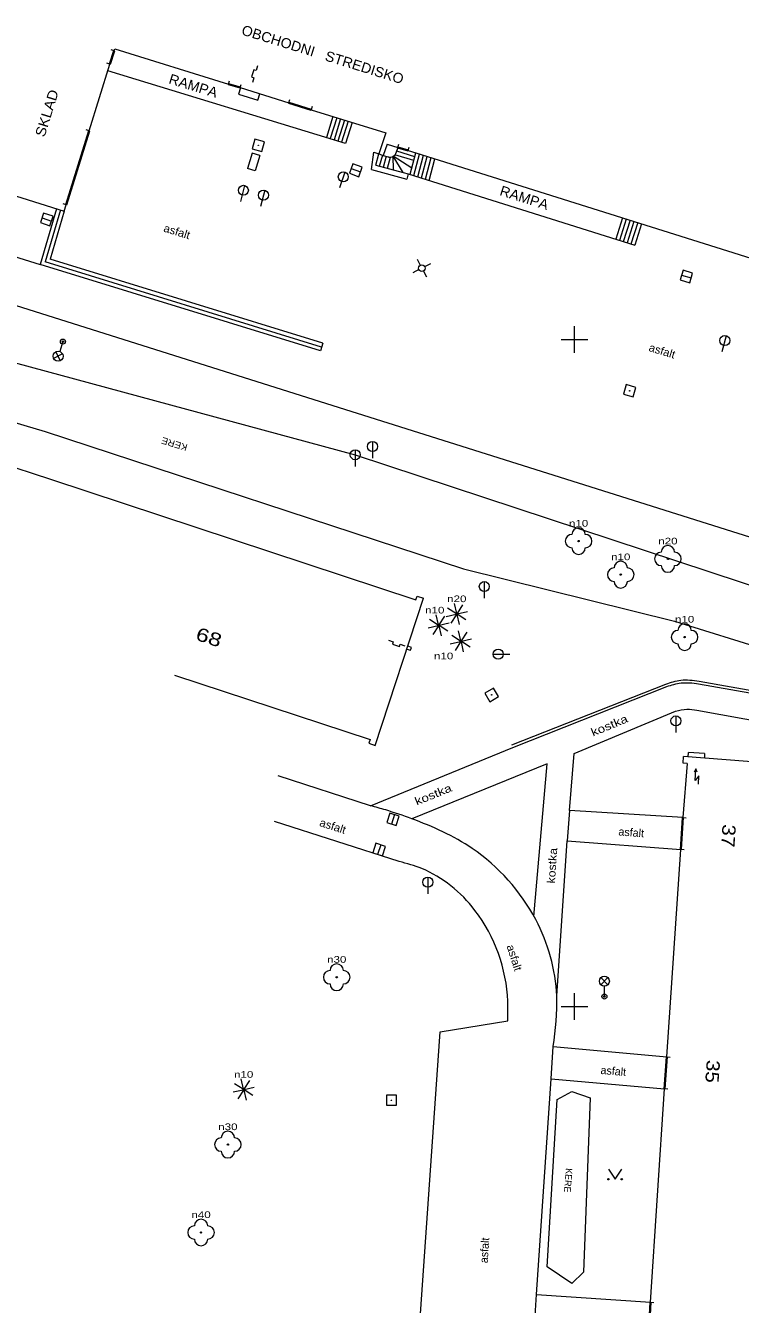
# Model space of a CAD drawing. Extents: x -670514 to -669423, y -1130798 to -1130123.
# Drawn here: x -670241.1 to -670187.6, y -1130272.3 to -1130176.5 of the extents above; entities that cross this region are included whole.
import ezdxf
from ezdxf.enums import TextEntityAlignment as Align

# ---------------------------------------------------------------- set-up
doc = ezdxf.new("R2010")
doc.units = 0
doc.header["$LTSCALE"] = 0.24
for name, color, linetype, lineweight in [('10', 7, 'Continuous', 13), ('11', 7, 'Continuous', 13), ('14', 7, 'Continuous', 13), ('21', 7, 'Continuous', 13), ('22', 7, 'Continuous', 13), ('24', 7, 'Continuous', 13), ('26', 7, 'Continuous', 13), ('27', 7, 'Continuous', 13), ('31', 7, 'Continuous', 13), ('33', 7, 'Continuous', 13), ('36', 7, 'Continuous', 13), ('5', 7, 'Continuous', 13), ('6', 7, 'Continuous', 13), ('61', 7, 'Continuous', 13), ('7', 7, 'Continuous', 13), ('9', 7, 'Continuous', 13)]:
    doc.layers.add(name, color=color, linetype=linetype, lineweight=lineweight)
for name, color, linetype in [('40', 7, 'Continuous'), ('41', 7, 'Continuous'), ('42', 7, 'Continuous'), ('44', 7, 'Continuous'), ('47', 7, 'Continuous')]:
    doc.layers.add(name, color=color, linetype=linetype)

msp = doc.modelspace()

# ---------------------------------------------------------------- linework, layer by layer
at = {"layer": '10'}
for p, q in [((-670217.167, -1130185.297), (-670234.972, -1130179.846)), ((-670218.107, -1130183.277), (-670218.598, -1130184.849)), ((-670217.821, -1130183.367), (-670218.312, -1130184.939)), ((-670217.535, -1130183.456), (-670218.026, -1130185.028)), ((-670217.248, -1130183.546), (-670217.739, -1130185.118)), ((-670216.962, -1130183.635), (-670217.453, -1130185.207)), ((-670216.676, -1130183.725), (-670217.167, -1130185.297)), ((-670271.263, -1130184.51), (-670240.044, -1130194.383)), ((-670215.221, -1130187.258), (-670215.048, -1130185.95)), ((-670215.048, -1130185.95), (-670214.669, -1130186.077)), ((-670214.896, -1130186.923), (-670214.669, -1130186.077)), ((-670214.606, -1130187), (-670214.379, -1130186.154)), ((-670214.342, -1130186.192), (-670213.96, -1130186.309)), ((-670214.316, -1130187.078), (-670214.089, -1130186.232)), ((-670213.566, -1130187.279), (-670213.595, -1130186.248)), ((-670212.837, -1130187.474), (-670213.595, -1130186.248)), ((-670212.203, -1130187.146), (-670213.595, -1130186.248)), ((-670212.053, -1130186.584), (-670213.458, -1130186.15)), ((-670213.235, -1130185.591), (-670213.391, -1130186.035)), ((-670211.975, -1130186.293), (-670213.323, -1130185.877)), ((-670212.327, -1130187.61), (-670211.898, -1130186.004)), ((-670212.042, -1130187.707), (-670211.612, -1130186.094)), ((-670211.756, -1130187.798), (-670211.325, -1130186.184)), ((-670211.469, -1130187.888), (-670211.038, -1130186.275)), ((-670214.896, -1130186.923), (-670212.837, -1130187.474)), ((-670214.026, -1130187.156), (-670213.803, -1130186.327)), ((-670211.183, -1130187.979), (-670210.752, -1130186.365)), ((-670210.896, -1130188.069), (-670210.465, -1130186.455)), ((-670215.221, -1130187.258), (-670212.579, -1130187.965)), ((-670212.837, -1130187.474), (-670212.474, -1130187.571)), ((-670212.474, -1130187.571), (-670212.579, -1130187.965)), ((-670212.474, -1130187.571), (-670195.49, -1130192.934)), ((-670196.414, -1130190.877), (-670196.92, -1130192.483)), ((-670196.128, -1130190.967), (-670196.634, -1130192.573)), ((-670195.842, -1130191.057), (-670196.348, -1130192.663)), ((-670195.556, -1130191.147), (-670196.062, -1130192.753)), ((-670195.27, -1130191.237), (-670195.776, -1130192.843)), ((-670194.984, -1130191.328), (-670195.49, -1130192.934)), ((-670216.254, -1130205.533), (-670257.775, -1130192.44)), ((-670164.577, -1130221.854), (-670216.254, -1130205.533)), ((-670190.705, -1130225.799), (-670161.27, -1130231.071)), ((-670190.834, -1130227.796), (-670161.644, -1130232.991)), ((-670215.282, -1130234.947), (-670222.22, -1130232.715)), ((-670213.137, -1130239.127), (-670222.492, -1130236.118)), ((-670191.884, -1130235.838), (-670200.384, -1130235.306)), ((-670210.077, -1130251.897), (-670205.001, -1130251.08)), ((-670212.326, -1130284.389), (-670210.077, -1130251.897)), ((-670201.594, -1130252.994), (-670193.086, -1130253.78)), ((-670201.752, -1130255.433), (-670193.25, -1130256.172)), ((-670203.011, -1130273.982), (-670202.849, -1130271.587)), ((-670202.849, -1130271.587), (-670194.302, -1130272.164))]:
    msp.add_line(p, q, dxfattribs=at)
for points in [[(-670215.282, -1130234.947), (-670204.632, -1130230.576), (-670193.082, -1130226.009)], [(-670200.384, -1130235.306), (-670200.036, -1130231.028), (-670192.434, -1130227.867)], [(-670203.041, -1130243.246), (-670202.049, -1130231.799), (-670212.195, -1130235.926)], [(-670201.332, -1130249.211), (-670200.558, -1130237.583), (-670192.04, -1130238.233)], [(-670202.849, -1130271.587), (-670201.752, -1130255.433), (-670201.594, -1130252.994)]]:
    msp.add_lwpolyline(points, dxfattribs=at)
for points in [[(-670213.96, -1130186.309), (-670213.924, -1130186.318), (-670213.455, -1130186.148), (-670213.419, -1130186.094), (-670213.391, -1130186.035)], [(-670193.082, -1130226.009), (-670192.021, -1130225.744), (-670190.705, -1130225.799)], [(-670192.434, -1130227.867), (-670191.576, -1130227.715), (-670190.834, -1130227.796)], [(-670201.594, -1130252.994), (-670201.332, -1130249.211), (-670202.91, -1130243.487), (-670207.671, -1130238.155), (-670212.195, -1130235.926), (-670214.153, -1130235.267), (-670215.282, -1130234.947)], [(-670205.001, -1130251.08), (-670205.001, -1130249.61), (-670207.465, -1130242.79), (-670211.445, -1130239.665), (-670213.137, -1130239.127)]]:
    msp.add_spline(points, degree=3, dxfattribs=at)
at = {"layer": '11'}
msp.add_line((-670200.384, -1130235.306), (-670200.558, -1130237.583), dxfattribs=at)
at = {"layer": '14'}
msp.add_line((-670192.5, -1130221.111), (-670161.234, -1130230.874), dxfattribs=at)
for points in [[(-670280.134, -1130185.532), (-670276.888, -1130192.263), (-670216.436, -1130208.635)], [(-670285.272, -1130193.354), (-670239.681, -1130206.896), (-670208.333, -1130217.194), (-670192.5, -1130221.111)], [(-670216.436, -1130208.635), (-670182.668, -1130219.789), (-670167.119, -1130226.229), (-670161.27, -1130231.071)]]:
    msp.add_lwpolyline(points, dxfattribs=at)
at = {"layer": '21'}
msp.add_lwpolyline([(-670201.31, -1130256.981), (-670200.193, -1130256.36), (-670198.826, -1130256.857), (-670199.323, -1130269.904), (-670200.193, -1130270.774), (-670202.057, -1130269.526)], close=True, dxfattribs=at)
at = {"layer": '22'}
for p, q in [((-670208.834, -1130220.532), (-670209.006, -1130219.778)), ((-670210.191, -1130221.382), (-670210.363, -1130220.628)), ((-670209.749, -1130220.732), (-670210.163, -1130221.388)), ((-670209.62, -1130220.752), (-670208.866, -1130220.58)), ((-670208.86, -1130220.552), (-670209.516, -1130220.138)), ((-670208.846, -1130220.606), (-670209.26, -1130221.262)), ((-670208.818, -1130220.612), (-670208.646, -1130221.366)), ((-670208.392, -1130219.882), (-670208.806, -1130220.538)), ((-670208.136, -1130221.006), (-670208.792, -1130220.592)), ((-670208.786, -1130220.564), (-670208.032, -1130220.392)), ((-670210.977, -1130221.602), (-670210.223, -1130221.43)), ((-670210.217, -1130221.402), (-670210.873, -1130220.988)), ((-670210.203, -1130221.456), (-670210.617, -1130222.112)), ((-670210.175, -1130221.462), (-670210.003, -1130222.216)), ((-670209.493, -1130221.856), (-670210.149, -1130221.442)), ((-670210.143, -1130221.414), (-670209.389, -1130221.242)), ((-670209.312, -1130222.801), (-670208.558, -1130222.629)), ((-670208.552, -1130222.601), (-670209.208, -1130222.187)), ((-670208.538, -1130222.655), (-670208.952, -1130223.311)), ((-670208.526, -1130222.581), (-670208.698, -1130221.827)), ((-670208.51, -1130222.661), (-670208.338, -1130223.415)), ((-670208.084, -1130221.931), (-670208.498, -1130222.587)), ((-670207.828, -1130223.055), (-670208.484, -1130222.641)), ((-670208.478, -1130222.613), (-670207.724, -1130222.441)), ((-670225.588, -1130256.407), (-670224.834, -1130256.235)), ((-670224.828, -1130256.207), (-670225.484, -1130255.793)), ((-670224.814, -1130256.261), (-670225.228, -1130256.917)), ((-670224.802, -1130256.187), (-670224.974, -1130255.433)), ((-670224.786, -1130256.267), (-670224.614, -1130257.021)), ((-670224.36, -1130255.537), (-670224.774, -1130256.193)), ((-670224.104, -1130256.661), (-670224.76, -1130256.247)), ((-670224.754, -1130256.219), (-670224, -1130256.047))]:
    msp.add_line(p, q, dxfattribs=at)
for centre, radius in [((-670199.697, -1130215.112), 0.05), ((-670193.005, -1130216.446), 0.05), ((-670196.541, -1130217.626), 0.05), ((-670208.826, -1130220.572), 0.04), ((-670210.183, -1130221.422), 0.04), ((-670208.518, -1130222.621), 0.04), ((-670191.753, -1130222.304), 0.05), ((-670217.824, -1130247.806), 0.05), ((-670224.794, -1130256.227), 0.04), ((-670225.98, -1130260.353), 0.05), ((-670227.99, -1130266.942), 0.05)]:
    msp.add_circle(centre, radius, dxfattribs=at)
for centre, start, end in [((-670200.197, -1130215.112), 90, 270), ((-670199.697, -1130214.612), 0, 180), ((-670199.197, -1130215.112), 270, 90), ((-670199.697, -1130215.612), 180, 0), ((-670193.505, -1130216.446), 90, 270), ((-670193.005, -1130215.946), 0, 180), ((-670192.505, -1130216.446), 270, 90), ((-670196.541, -1130217.126), 0, 180), ((-670193.005, -1130216.946), 180, 0), ((-670197.041, -1130217.626), 90, 270), ((-670196.041, -1130217.626), 270, 90), ((-670196.541, -1130218.126), 180, 0), ((-670191.753, -1130221.804), 0, 180), ((-670192.253, -1130222.304), 90, 270), ((-670191.253, -1130222.304), 270, 90), ((-670191.753, -1130222.804), 180, 0), ((-670218.324, -1130247.806), 90, 270), ((-670217.824, -1130247.306), 0, 180), ((-670217.324, -1130247.806), 270, 90), ((-670217.824, -1130248.306), 180, 0), ((-670226.48, -1130260.353), 90, 270), ((-670225.98, -1130259.853), 0, 180), ((-670225.48, -1130260.353), 270, 90), ((-670225.98, -1130260.853), 180, 0), ((-670228.49, -1130266.942), 90, 270), ((-670227.99, -1130266.442), 0, 180), ((-670227.49, -1130266.942), 270, 90), ((-670227.99, -1130267.442), 180, 0)]:
    msp.add_arc(centre, 0.5, start, end, dxfattribs=at)
at = {"layer": '24'}
for p, q in [((-670191.477, -1130231.281), (-670191.461, -1130230.961)), ((-670190.255, -1130231.022), (-670191.461, -1130230.961)), ((-670190.255, -1130231.022), (-670190.273, -1130231.378))]:
    msp.add_line(p, q, dxfattribs=at)
for points in [[(-670223.761, -1130179.491), (-670223.872, -1130179.842), (-670224.046, -1130179.787), (-670224.211, -1130180.314), (-670224.037, -1130180.37), (-670224.146, -1130180.721)], [(-670225.035, -1130181.121), (-670225.191, -1130181.617), (-670223.723, -1130182.055), (-670223.574, -1130181.577)], [(-670213.945, -1130222.548), (-670213.596, -1130222.664), (-670213.653, -1130222.838), (-670213.128, -1130223.01), (-670213.07, -1130222.836), (-670212.72, -1130222.95)], [(-670212.569, -1130223.203), (-670212.291, -1130223.293), (-670212.223, -1130223.084), (-670212.5, -1130222.993)], [(-670190.821, -1130232.439), (-670190.918, -1130232.189), (-670191.04, -1130232.428)], [(-670190.725, -1130233.326), (-670190.694, -1130232.701), (-670190.962, -1130233.063), (-670190.918, -1130232.189)]]:
    msp.add_lwpolyline(points, dxfattribs=at)
at = {"layer": '26'}
for points in [[(-670224.165, -1130185.695), (-670223.444, -1130185.9), (-670223.239, -1130185.179), (-670223.96, -1130184.974)], [(-670196.339, -1130204.103), (-670195.617, -1130204.307), (-670195.413, -1130203.585), (-670196.135, -1130203.381)], [(-670206.352, -1130227.149), (-670205.703, -1130226.772), (-670206.08, -1130226.123), (-670206.729, -1130226.5)], [(-670214.097, -1130257.404), (-670213.347, -1130257.404), (-670213.347, -1130256.654), (-670214.097, -1130256.654)]]:
    msp.add_lwpolyline(points, close=True, dxfattribs=at)
for centre in [(-670223.7019, -1130185.437), (-670195.8759, -1130203.844), (-670206.216, -1130226.636), (-670213.7219, -1130257.029)]:
    msp.add_circle(centre, 0.02, dxfattribs=at)
at = {"layer": '27'}
for p, q in [((-670216.75, -1130187.182), (-670216.046, -1130187.438)), ((-670217.208, -1130187.45), (-670217.621, -1130188.63)), ((-670224.723, -1130188.45), (-670225.041, -1130189.66)), ((-670223.218, -1130188.812), (-670223.541, -1130190.021)), ((-670239.908, -1130190.873), (-670239.198, -1130191.115)), ((-670191.975, -1130195.172), (-670191.255, -1130195.378)), ((-670188.64, -1130199.714), (-670188.976, -1130200.918)), ((-670216.436, -1130208.26), (-670216.436, -1130209.51)), ((-670215.145, -1130207.641), (-670215.145, -1130208.891)), ((-670206.763, -1130218.143), (-670206.763, -1130219.393)), ((-670206.097, -1130223.589), (-670204.847, -1130223.589)), ((-670192.408, -1130228.216), (-670192.408, -1130229.466)), ((-670213.492, -1130235.611), (-670213.722, -1130236.325)), ((-670214.526, -1130237.881), (-670214.756, -1130238.595)), ((-670210.996, -1130240.302), (-670210.996, -1130241.552))]:
    msp.add_line(p, q, dxfattribs=at)
for points in [[(-670216.878, -1130187.533), (-670216.174, -1130187.79), (-670215.917, -1130187.085), (-670216.622, -1130186.828)], [(-670240.029, -1130191.227), (-670239.319, -1130191.469), (-670239.077, -1130190.759), (-670239.787, -1130190.517)], [(-670192.079, -1130195.531), (-670191.358, -1130195.738), (-670191.151, -1130195.017), (-670191.872, -1130194.81)], [(-670213.848, -1130235.496), (-670214.078, -1130236.21), (-670213.364, -1130236.44), (-670213.134, -1130235.726)], [(-670214.882, -1130237.766), (-670215.112, -1130238.48), (-670214.398, -1130238.71), (-670214.168, -1130237.996)]]:
    msp.add_lwpolyline(points, close=True, dxfattribs=at)
for centre in [(-670217.3317, -1130187.8042), (-670224.8177, -1130188.8132), (-670223.3147, -1130189.1752), (-670188.7407, -1130200.0752), (-670216.4356, -1130208.6351), (-670215.1446, -1130208.0161), (-670206.7626, -1130218.5181), (-670205.7219, -1130223.5886), (-670192.4076, -1130228.5911), (-670210.9956, -1130240.6771)]:
    msp.add_circle(centre, 0.375, dxfattribs=at)
at = {"layer": '31'}
for p, q in [((-670211.665, -1130194.758), (-670212.108, -1130194.99)), ((-670211.79, -1130193.976), (-670211.558, -1130194.422)), ((-670211.328, -1130194.864), (-670211.096, -1130195.309)), ((-670211.221, -1130194.528), (-670210.777, -1130194.298))]:
    msp.add_line(p, q, dxfattribs=at)
msp.add_circle((-670211.4427, -1130194.6437), 0.25, dxfattribs=at)
at = {"layer": '33'}
for p, q in [((-670238.338, -1130200.158), (-670238.583, -1130200.893)), ((-670238.366, -1130201.081), (-670239.036, -1130201.417)), ((-670238.533, -1130201.584), (-670238.869, -1130200.914)), ((-670198.034, -1130247.837), (-670197.504, -1130248.367)), ((-670198.034, -1130248.367), (-670197.504, -1130247.837)), ((-670197.769, -1130249.252), (-670197.769, -1130248.477))]:
    msp.add_line(p, q, dxfattribs=at)
for centre, radius in [((-670238.338, -1130200.158), 0.19), ((-670238.338, -1130200.158), 0.05), ((-670238.7011, -1130201.2492), 0.375), ((-670197.769, -1130248.102), 0.375), ((-670197.769, -1130249.252), 0.19), ((-670197.769, -1130249.252), 0.05)]:
    msp.add_circle(centre, radius, dxfattribs=at)
at = {"layer": '36'}
msp.add_lwpolyline([(-670197.464, -1130262.196), (-670196.964, -1130262.946), (-670196.464, -1130262.196)], dxfattribs=at)
for centre in [(-670197.464, -1130262.946), (-670196.464, -1130262.946)]:
    msp.add_circle(centre, 0.05, dxfattribs=at)
at = {"layer": '5'}
for p, q in [((-670234.498, -1130178.344), (-670234.453, -1130178.202)), ((-670234.453, -1130178.202), (-670225.922, -1130180.845)), ((-670236.363, -1130184.348), (-670234.824, -1130179.368)), ((-670225.062, -1130181.113), (-670221.414, -1130182.252)), ((-670219.731, -1130182.771), (-670214.147, -1130184.514)), ((-670258.77, -1130183.929), (-670238.242, -1130190.373)), ((-670224.162, -1130186.019), (-670224.51, -1130187.184)), ((-670223.587, -1130186.191), (-670224.162, -1130186.019)), ((-670223.587, -1130186.191), (-670223.935, -1130187.356)), ((-670214.043, -1130185.343), (-670214.342, -1130186.192)), ((-670214.043, -1130185.343), (-670213.235, -1130185.591)), ((-670212.471, -1130185.827), (-670211.898, -1130186.004)), ((-670211.898, -1130186.004), (-670184.876, -1130194.51)), ((-670223.935, -1130187.356), (-670224.51, -1130187.184)), ((-670238.242, -1130190.373), (-670238.093, -1130189.895)), ((-670280.195, -1130197.191), (-670239.268, -1130210.463)), ((-670239.268, -1130210.463), (-670211.888, -1130219.514)), ((-670214.933, -1130230.426), (-670211.319, -1130219.385)), ((-670211.888, -1130219.514), (-670211.794, -1130219.229)), ((-670211.794, -1130219.229), (-670211.319, -1130219.385)), ((-670229.981, -1130225.148), (-670215.314, -1130229.985)), ((-670215.314, -1130229.985), (-670215.408, -1130230.27)), ((-670215.408, -1130230.27), (-670214.933, -1130230.426)), ((-670191.873, -1130231.75), (-670191.833, -1130231.252)), ((-670178.563, -1130232.322), (-670191.833, -1130231.252)), ((-670191.574, -1130231.774), (-670191.884, -1130235.838)), ((-670191.574, -1130231.774), (-670191.873, -1130231.75)), ((-670193.086, -1130253.78), (-670192.04, -1130238.233)), ((-670194.302, -1130272.164), (-670193.25, -1130256.172))]:
    msp.add_line(p, q, dxfattribs=at)
msp.add_lwpolyline([(-670214.147, -1130184.514), (-670214.669, -1130186.077), (-670214.342, -1130186.192)], dxfattribs=at)
at = {"layer": '6', "lineweight": 35}
for p, q in [((-670234.498, -1130178.344), (-670234.824, -1130179.368)), ((-670225.922, -1130180.845), (-670225.062, -1130181.113)), ((-670221.414, -1130182.252), (-670219.731, -1130182.771)), ((-670238.093, -1130189.895), (-670236.363, -1130184.348)), ((-670212.471, -1130185.827), (-670213.235, -1130185.591)), ((-670191.884, -1130235.838), (-670192.04, -1130238.233)), ((-670193.086, -1130253.78), (-670193.25, -1130256.172)), ((-670194.302, -1130272.164), (-670194.444, -1130274.555))]:
    msp.add_line(p, q, dxfattribs=at)
at = {"layer": '6'}
for p, q in [((-670234.498, -1130178.344), (-670234.736, -1130178.269)), ((-670234.824, -1130179.368), (-670235.062, -1130179.292)), ((-670225.922, -1130180.845), (-670225.847, -1130180.606)), ((-670225.062, -1130181.113), (-670224.988, -1130180.874)), ((-670221.414, -1130182.252), (-670221.34, -1130182.013)), ((-670219.657, -1130182.532), (-670219.731, -1130182.771)), ((-670236.363, -1130184.348), (-670236.601, -1130184.273)), ((-670213.235, -1130185.591), (-670213.162, -1130185.352)), ((-670212.471, -1130185.827), (-670212.397, -1130185.588)), ((-670238.093, -1130189.895), (-670238.331, -1130189.821)), ((-670191.884, -1130235.838), (-670191.634, -1130235.854)), ((-670191.79, -1130238.249), (-670192.04, -1130238.233)), ((-670193.086, -1130253.78), (-670192.836, -1130253.797)), ((-670193, -1130256.189), (-670193.25, -1130256.172)), ((-670194.302, -1130272.164), (-670194.052, -1130272.178))]:
    msp.add_line(p, q, dxfattribs=at)
at = {"layer": '61'}
for p, q in [((-670200, -1130201), (-670200, -1130199)), ((-670201, -1130200), (-670199, -1130200)), ((-670200, -1130251), (-670200, -1130249)), ((-670201, -1130250), (-670199, -1130250))]:
    msp.add_line(p, q, dxfattribs=at)
at = {"layer": '7'}
for p, q in [((-670238.814, -1130190.193), (-670240.044, -1130194.383)), ((-670238.242, -1130190.373), (-670239.302, -1130193.984)), ((-670219.044, -1130200.846), (-670240.044, -1130194.383)), ((-670218.868, -1130200.273), (-670239.302, -1130193.984)), ((-670218.868, -1130200.273), (-670219.044, -1130200.846))]:
    msp.add_line(p, q, dxfattribs=at)
at = {"layer": '9'}
for p, q in [((-670238.529, -1130190.288), (-670239.672, -1130194.183)), ((-670218.956, -1130200.559), (-670239.672, -1130194.183)), ((-670204.705, -1130230.39), (-670193.155, -1130225.823)), ((-670190.669, -1130225.602), (-670161.234, -1130230.874))]:
    msp.add_line(p, q, dxfattribs=at)
msp.add_spline([(-670193.155, -1130225.823), (-670192.042, -1130225.533), (-670190.669, -1130225.602)], degree=3, dxfattribs=at)

# ---------------------------------------------------------------- texts
at = {"layer": '22', "width": 1.1}
msp.add_text('KERE', height=0.499, rotation=163.113, dxfattribs=at).set_placement((-670229.9155, -1130207.5923), align=Align.CENTER)
at = {"layer": '22', "width": 1.3}
for s, p in [('n10', (-670199.6975, -1130214.026)), ('n20', (-670193.0045, -1130215.36)), ('n10', (-670196.5415, -1130216.54)), ('n20', (-670208.8265, -1130219.686)), ('n10', (-670210.4775, -1130220.536)), ('n10', (-670191.7535, -1130221.218)), ('n10', (-670209.8105, -1130223.969)), ('n30', (-670217.8235, -1130246.72)), ('n10', (-670224.7945, -1130255.341)), ('n30', (-670225.9795, -1130259.267)), ('n40', (-670227.9895, -1130265.856))]:
    msp.add_text(s, height=0.499, dxfattribs=at).set_placement(p, align=Align.CENTER)
at = {"layer": '40'}
for s, rotation, width, p in [('asfalt', 342.893, 1.05, (-670229.8842, -1130192.1886)), ('asfalt', 342.893, 1.05, (-670193.5262, -1130201.1386)), ('kostka', 22.578, 1.25, (-670197.2807, -1130229.2072)), ('kostka', 22.135, 1.25, (-670210.483, -1130234.387)), ('asfalt', 342.17, 1.05, (-670218.2059, -1130236.7612)), ('kostka', 86.192, 1.15, (-670201.3846, -1130239.4604)), ('asfalt', 287.942, 1.05, (-670204.7979, -1130246.4356))]:
    msp.add_text(s, height=0.6, rotation=rotation, dxfattribs=dict(at, width=width)).set_placement(p, align=Align.CENTER)
for rotation, p in [(355.636, (-670195.7743, -1130237.2454)), (355.032, (-670197.1195, -1130255.1335)), (86.115, (-670206.45, -1130268.3008))]:
    msp.add_text('asfalt', height=0.6, rotation=rotation, dxfattribs=at).set_placement(p, align=Align.CENTER)
at = {"layer": '41'}
for s, rotation, width, p in [('OBCHODNI   STREDISKO', 342.786, 1.05, (-670218.9835, -1130178.989)), ('SKLAD', 72.678, 1.1, (-670239.1832, -1130183.1372))]:
    msp.add_text(s, height=0.75, rotation=rotation, dxfattribs=dict(at, width=width)).set_placement(p, align=Align.CENTER)
at = {"layer": '42', "width": 1.05}
for rotation, p in [(342.978, (-670228.6778, -1130181.3302)), (342.476, (-670203.8824, -1130189.7262))]:
    msp.add_text('RAMPA', height=0.75, rotation=rotation, dxfattribs=at).set_placement(p, align=Align.CENTER)
at = {"layer": '44'}
for s, rotation, width, p in [('68', 341.748, 1.3, (-670227.5531, -1130222.79)), ('37', 266.273, 1.15, (-670188.9643, -1130237.173)), ('35', 266.078, 1.15, (-670190.1519, -1130254.8368))]:
    msp.add_text(s, height=1, rotation=rotation, dxfattribs=dict(at, width=width)).set_placement(p, align=Align.CENTER)
at = {"layer": '47'}
msp.add_text('KERE', height=0.5, rotation=265.409, dxfattribs=at).set_placement((-670200.7207, -1130263.0115), align=Align.CENTER)

doc.saveas('drawing.dxf')
